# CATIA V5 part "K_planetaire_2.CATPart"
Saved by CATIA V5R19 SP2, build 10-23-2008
Part number: planetaire 2
Source: Unknown
Publications: "Face"
Material "Aucun"
Bounding box of the stored display mesh (mm): x -121.726 to 121.726, y -121.726 to 121.726, z -25 to 22.385
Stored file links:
  G:\Khaled_CFAO_2011\ST2M\ST2M_GR1\mponsin\Khaled\CAD_ThinkMOTION\K_planetaire_2.CATPart
  C:\Program Files\Dassault Systemes\B20\win_b64\startup\materials\French\Catalog.CATMaterial
  C:\Users\Socar\Documents\thinkmotion\Final\Diff2.CATProduct
  G:\Khaled_CFAO_2011\ST2M\ST2M_GR1\mponsin\Khaled\CAD_ThinkMOTION\K_mponsin.CATProduct
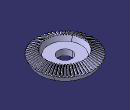
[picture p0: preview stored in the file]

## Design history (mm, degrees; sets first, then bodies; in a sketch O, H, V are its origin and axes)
Parameters
  Z1 = 60 {= External.Zp}
  delta = 63.4349 deg {= atan(External.Zp /External.Zs )}
  a = 20 deg
  m = 4 mm {= External.Module}
  ld = 44.7214 mm {= m *Z1 /(3*2*sin(delta ))}
  dZ = 0 mm
  p = 12.5664 mm {= m * PI}
  rp = 120 mm {= m * Z1 / 2}
  rc = 268.3282 mm {= rp / cos( delta )}
  rb = 252.146 mm {= rc * cos( a )}
  lc = 300 mm {= rc / sin( delta )}
  ha = 4 mm {= m}
  hf = 5 mm {= 1.25 * m}
  rr = 1.2196 mm {= Set2.Offset * 0.7763}
  tc = -0.7576 deg
  ratio = 0.666667 {= 1 - ld / lc / cos( delta )}
External parameters (linked from other documents)
  External.Zp = 60
  External.Zs = 30
  External.Module = 4 mm
  `External.R cardan` = 30 mm
Intersect1 "coin de fond": ToIntersect1 Project1, ToIntersect2 Circle4
Point1: type OnCurve, Support Line7, Length 5 {= hf}
Set1 "cones primitifs"
  Line1 "Axe Z": stored without definition
  Point2 "sommet arriere": (0, 0, -240 {= dZ - rp * tan( delta )})
  Point3 "sommet avant": type OnCurve, Support Line1, RefPoint Point2, Length 300 {= lc}
  Line2: type PtPt, FirstPoint Point2, SecondPoint Point3
  Line3: type Angle, RefPoint Point3, Curve Line2, Support zx-plane, Start 0, End 134.1641 {= lc * cos( delta )}, Angle -63.4349 {= -delta}
  Line4: type PtPt, FirstPoint Point2, SecondPoint vertex of Line3, Start 0
  Plane1 "plan_primitif": type OffsetPt, RefPlane xy-plane, RefPoint vertex of Line3
  Intersect2: ToIntersect1 Plane1, ToIntersect2 Line2
  Circle1 "arc primitif": type CtrPt, Start 0, End 30, Center Intersect2, Support Plane1, RefPoint vertex of Line3
  Circle2 "cercle primitif": type CtrRad, Start 0, End 90, Center Intersect2, Support Plane1, Radius 120 {= rp}, FirstDirection (1, 0, 0)
Set2 "profil dent"
  Point4 "point 0": type OnPlane, Support Plane2, RefPoint Point2, H 252.146, V 0, Direction (1, 0, 0)
  Point5 "point 1": type OnPlane, Support Plane2, RefPoint Point2, H 264.2836, V 2.5804, Direction (1, 0, 0)
  Point6 "point 2": type OnPlane, Support Plane2, RefPoint Point2, H 297.112, V 20.0368, Direction (1, 0, 0)
  Point7 "point 3": type OnPlane, Support Plane2, RefPoint Point2, H 340.4641, V 64.3079, Direction (1, 0, 0)
  Curve1: Elements (Point4; Point5; Point6; Point7)
  Extrapol1: ToExtrapol Point4, Support Curve1, Length 8 {= 2 * m}
  Plane2: type Normal, Curve Line3, RefPoint Point2
  Symmetry1: Reference vertex of Line3, ToTransfor Point2
  Line5: type PtPt, FirstPoint Point2, SecondPoint Symmetry1
  Point8: type OnCurve, Support Line5, Ratio 0.25
  Line6: type PtPt, FirstPoint Point8, SecondPoint vertex of Line5
  Revol1: Element1 Line6, Line Line1, Angle1 0
  Project1: ToProject Extrapol1, Support Revol1, Direction Line3
  Intersect3: ToIntersect1 Circle1, ToIntersect2 Project1
  Plane3 "plan contact": type 1Line1Pt, RefPoint Intersect3, Line Line1
  Circle3 "cercle primitif": type CtrPt, Start 1.5 {= 90deg / Z1}, End -1.5 {= -90deg / Z1}, Center Intersect2, Support Plane1, RefPoint Intersect3
  Plane4 "plan median": type 1Line1Pt, RefPoint vertex of Circle3, Line Line1
  Line7 "droite debut": type PtPt, FirstPoint vertex of Circle3, SecondPoint Point2
  Plane5 "plan_fond": type OffsetPt, RefPlane xy-plane, RefPoint Point1
  Intersect4: ToIntersect1 Plane5, ToIntersect2 Line2
  Circle4 "cercle de fond": type CtrPt, Start 0, End 30, Center Intersect4, Support Plane5, RefPoint Point1
  Point9: type OnCurve, Support Line7, Length -4 {= -ha}
  Plane6 "plan_tete": type OffsetPt, RefPlane xy-plane, RefPoint Point9
  Intersect5: ToIntersect1 Plane6, ToIntersect2 Line2
  Circle5 "cercle de tete": type CtrPt, Start 0, End 30, Center Intersect5, Support Plane6, RefPoint Point9
  Split1 "segment flanc": ToCut Project1, Cutting Plane5
  Split2 "segment fond": ToCut Circle4, Cutting Project1
  Corner1: Element1 Split1, Element2 Split2, Support Revol1, Radius 1.194 {= Set2.Offset * 0.76}
  Symmetry2: Reference Plane4, ToTransfor Corner1
  Trim1: Element1 Corner1, Element2 Circle5
  Trim2: Element1 Trim1, Element2 Symmetry2
Set3 "surface dent"
  Point10 "fin denture": type OnCurve, Support Line3, Length 44.7214 {= ld}
  Scaling1: Reference Point3, Ratio 0.666667 {= ratio}, ToTransfor Trim2
  Line8: type PtPt, FirstPoint vertex of Scaling1, SecondPoint Point1
  Line9: type PtPt, FirstPoint vertex of Scaling1, SecondPoint vertex of Trim2
  Loft1: Sections (Trim2; Scaling1), Guides (Line8; Line9)
  CircPattern1: of Loft1, instances 60 {= Z1}, angular step 6 {= 360.0*1 deg/CircPattern1.AngularNumber}, axis from Line2
Set4 "flanc dent"
  CircPattern2: of Trim2, instances 60 {= Z1}, angular step 6 {= 360.0*1 deg/CircPattern2.AngularNumber}, axis from Line2
  Join1: Elements (CircPattern2; Trim2)
  Split3: ToCut Revol1, Cutting Join1
  Scaling2: Reference Point3, Ratio 0.666667 {= ratio}, ToTransfor Split3
  Fill1: Boundary edge of Scaling2
  Join2: Elements (Split3; CircPattern1; Scaling2; Fill1; Loft1)
Body1 (main body)
  Sketch1 on zx-plane, origin (0, 0, 0), H (-1, 0, 0), V (0, 0, 1)
    point P1 (-60, -120)
    line L1 (0, 0) -> (0, -123.9213)
    line L2 (0, -123.9213) -> (-60, -123.9213)
    line L3 (-60, -123.9213) -> (-60, -120)
    reference projected point E1 (-60, -120) from Point8
    line L4 (-60, -120) -> (-120, 0)
    point P5 (-120, 0)
    line L5 (0, 0) -> (-120, 0)
    reference projected point E2 (-120, 0) from vertex of Line4
    horizontal: L2 H, L5 H
    vertical: L1 V, L3 V
    coincidence: P1 E1, L1 V, P5 E2
  Shaft1: profile Sketch1, axis Line1, angle 360
  CloseSurface1: CloseElement Join2
  Sketch2 on xy-plane, origin (0, 0, 0), H (1, 0, 0), V (0, 1, 0)
    circle A1 centre (0, 0) radius 30
    radius A1 = 30 {= `External.R cardan`}
  Pocket1: profile Sketch2, direction (0, 0, 1), through (limit type 6), opposite side through (limit type 6)
  Body2
    Sketch3 on zx-plane, origin (0, 0, 0), H (-1, 0, 0), V (0, 0, 1)
      line L1 (0, -240) -> (393.9525, -20)
      point P1 (0, -240)
      point P2 (393.9525, -20)
      line L2 (393.9525, -20) -> (90, -20)
      point P3 (393.9525, -20)
      line L3 (90, -20) -> (90, -25)
      line L4 (90, -25) -> (0, -25)
      point P6 (0, -25)
      line L5 (0, -25) -> (0, -240)
      reference projected point E1 (0, -240) from Point2
      length L3 = 5
      length L4 = 90
      distance L2 H = 20
      length L2 = 303.9525
      coincidence: P1 V, P3 L1, P6 V, P2 P3, P1 E1
      horizontal: L2 H, L4 H
      vertical: L3 V, L5 V
    Shaft2: profile Sketch3, axis Sketch3.L5, angle 360
  Remove1: tool Body2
